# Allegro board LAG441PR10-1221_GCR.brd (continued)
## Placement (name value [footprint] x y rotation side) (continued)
PR180  1M_0402_1%  [R_0402]  16.89 42.61 180 top
PR181  499K_0402_1%  [R_0402]  21.2 40.9 90 top
PR182  47K_0402_1%  [R_0402]  16.89 44.26 180 top
PR183  499K_0402_1%  [R_0402]  26.25 46.6 270 top
PR184  221K_0402_1%  [R_0402]  19.4 44.5 90 top
PR185  1M_0402_1%  [R_0402]  43.22 13.22 270 top
PR186  0_0402_5%  [R0402_0OHM]  16.03 41.87 270 top
PR187  47K_0402_1%  [R_0402]  22.85 42.69 90 top
PR188  0_0402_5%  [R0402_0OHM]  25.27 43.53 270 top
PR189  1M_0201_1%  [R_0201]  15.72 40.1 180 top
PR190  200K_0402_1%  [R_0402]  25.48 45.69 90 top
PR191  1M_0201_1%  [R_0201]  25.96 43.68 0 top
PR192  200K_0402_1%  [R_0402]  20.44 41.81 270 top
PR193  200K_0402_1%  [R_0402]  21.2 42.59 90 top
PR194  200K_0402_1%  [R_0402]  21.06 45.51 270 top
PR195  100_0402_1%  [R_0402]  39.84 19.7 0 top
PR196  100_0402_1%  [R_0402]  39.84 18.94 0 top
PR197  0_0402_5%  [R0402_0OHM]  40.75 18.18 180 top
PR199  0_0402_5%  [R0402_0OHM]  22.8 40 270 top
PR200  0.01_1206_1%  [R_1206_4P-D]  22.38 39.17 180 bottom
PR201  442K_0402_1%  [R_0402]  21.55 41.52 270 bottom
PR202  1_0402_1%  [R_0402]  26.26 23.69 270 top
PR203  1_0402_1%  [R_0402]  27.15 23.69 270 top
PR204  100K_0402_1%  [R_0402]  21.49 43.26 0 bottom
PR205  2.2_0603_5%  [R_0603]  30.45 22.37 180 top
PR206  2_1206_5%  [R_1206]  23.79 25.21 270 top
PR207  4.7_0402_1%  [R_0402]  34.12 20.59 0 top
PR208  2_1206_5%  [R_1206]  19.4 20.66 0 top
PR209  0_0201_5%  [R_0201]  23.54 18.83 0 top
PR210  2.2_0603_5%  [R_0603]  33.5 19.58 0 top
PR211  0.005_1206_1%  [R_1206_4P-D]  44.93 27.83 270 bottom
PR212  0_0201_5%  [R0201_0OHM]  23.54 18.26 0 top
PR213  0_0402_5%  [R0402_0OHM]  23.54 17.57 0 top
PR214  0_0402_5%  [R0402_0OHM]  23.54 16.81 0 top
PR215  4.7_1206_5%  [R_1206]  24.73 32.08 270 top
PR216  4.7_1206_5%  [R_1206]  34.3 32.42 270 top
PR217  75_0402_5%  [R_0402]  23.54 16.05 0 top
PR218  0_0402_5%  [R0402_0OHM]  33.91 17.16 0 top
PR219  100K_0402_1%  [R_0402]  21.92 15.28 0 top
PR220  0_0402_5%  [R0402_0OHM]  23.54 15.28 0 top
PR221  1_0402_1%  [R_0402]  34.82 16.4 180 top
PR222  1_0402_1%  [R_0402]  35.62 15.55 270 top
PR223  0_0402_5%  [R0402_0OHM]  26.84 10.21 180 top
PR224  1M_0402_1%  [R_0402]  23.54 14.52 0 top
PR225  154K_0402_1%  [R_0402]  22.83 14.52 180 top
PR226  105K_0402_1%  [R_0402]  26.01 13.85 270 top
PR227  1M_0402_1%  [R_0402]  25.88 11.15 90 top
PR228  0_0201_5%  [R0201_0OHM]  25.27 13.33 90 top
PR229  0_0201_5%  [R0201_0OHM]  29.44 13.57 90 top
PR230  1K_0402_1%  [R_0402]  28.67 13.85 270 top
PR231  499_0402_1%  [R_0402]  26.77 13.85 270 top
PR232  10K_0201_5%  [R_0201]  29.44 12.95 270 top
PR233  0_0402_5%  [R0402_0OHM]  27.78 10.14 90 top
PR234  0_0402_5%  [R0402_0OHM]  28.67 10.14 90 top
PR236  100_0402_1%  [R_0402]  32.12 13.69 0 top
PR300  0_0603_5%  [R_0603]  200.8 46.03 90 bottom
PR302  52.3K_0402_1%  [R_0402]  202.16 42.13 270 bottom
PR304  11.5K_0402_1%  [R_0402]  201.4 41.22 90 bottom
PR306  0_0402_5%  [R0402_0OHM]  204.14 40.34 180 bottom
PR307  243K_0402_1%  [R_0402]  201.51 43.57 270 top
PR308  4.53K_0402_1%  [R_0402]  200.06 43.63 90 top
PR309  4.7_0805_5%  [R_0805]  198.13 55.5 0 bottom
PR310  10K_0402_1%  [R_0402]  203.22 39.58 0 bottom
PR400  0_0402_5%  [R_0402]  44.44 44.09 180 bottom
PR401  3.3_0603_1%  [R_0603]  40.24 42.38 180 top
PR402  4.7_0805_5%  [R_0805]  38.01 39.68 180 top
PR403  100K_0402_5%  [R_0402]  42.53 39.52 180 top
PR404  0_0402_5%  [R0402_0OHM]  42.71 44.04 270 bottom
PR408  0_0402_5%  [R_0402]  300.06 59.2 270 bottom
PR409  3.3_0603_1%  [R_0603]  298.04 62.69 90 top
PR410  4.7_0805_5%  [R_0805]  298.19 66.57 180 top
PR411  100K_0402_5%  [R_0402]  294.05 58.82 180 bottom
PR412  100K_0402_5%  [R_0402]  297.65 59.88 0 top
PR413  100K_0402_5%  [R_0402]  41.95 43.12 90 bottom
PR414  100K_0402_5%  [R_0402]  298.56 59.07 180 top
PR501  499_0402_1%  [R_0402]  113.64 26.33 0 bottom
PR502  40.2K_0402_1%  [R_0402]  115.45 27.21 270 bottom
PR503  150K_0201_5%  [R_0201]  113.64 21.01 180 bottom
PR504  20K_0402_1%  [R_0402]  115.89 25.55 180 bottom
PR506  4.7_0603_5%  [R_0603]  110.12 21.44 180 bottom
PR507  2.2_0402_1%  [R_0402]  112.15 22.17 270 bottom
PR510  274K_0402_1%  [R_0402]  112.87 25.5 90 bottom
PR600  75_0402_5%  [R_0402]  46.65 26.29 90 bottom
PR602  4.7_0603_5%  [R_0603]  47.94 20.11 0 top
PR603  0_0603_5%  [R_0603]  47.98 22.5 180 top
PR604  0_0402_5%  [R_0402]  46.48 24.67 90 top
PR605  100K_0402_1%  [R_0402]  50.64 24.27 180 top
PR606  100K_0402_1%  [R_0402]  48.86 24.3 270 top
PR607  0_0402_5%  [R_0402]  46.65 25.49 270 bottom
PR701  549K_0402_1%  [R_0402]  126.05 42.02 180 bottom
PR702  100K_0402_5%  [R_0402]  123.99 35.69 90 bottom
PR703  100K_0402_5%  [R_0402]  124.75 35.69 90 bottom
PR704  100K_0402_5%  [R_0402]  130.72 40.95 180 bottom
PR705  1M_0402_5%  [R_0402]  122.82 39.45 90 bottom
PR706  100K_0402_5%  [R_0402]  129.81 40.09 0 bottom
PR800  4.7_0805_5%  [R_0805]  123.9 57.28 180 top
PR801  0_0402_5%  [R_0402]  124.65 56.01 0 bottom
PR803  15K_0402_1%  [R_0402]  118.02 54.44 0 bottom
PR806  20K_0402_1%  [R_0402]  118.91 53.65 180 bottom
PR807  0_0402_5%  [R_0402]  118.01 52.07 0 bottom
PR808  0_0402_5%  [R_0402]  118.91 52.86 180 bottom
PR900  2M_0402_5%  [R_0402]  40.91 61.37 270 top
PR901  0_0402_5%  [R0402_0OHM]  46.33 54.07 270 bottom
PR902  4.7_0402_5%  [R_0402]  39.73 57.84 90 bottom
PR903  0_0402_5%  [R0402_0OHM]  40.65 57.7 180 top
PR904  0_0402_5%  [R0402_0OHM]  40.66 56.92 180 top
PR905  133K_0402_1%  [R_0402]  40.06 60.43 90 top
PR906  0_0402_5%  [R0402_0OHM]  40.66 56.13 180 top
PR907  0_0402_5%  [R0402_0OHM]  40.65 55.37 180 top
PR908  10K_0402_1%  [R_0402]  43.84 53.28 90 top
PR909  10K_0402_1%  [R_0402]  41.5 53.28 90 top
PR910  10K_0402_1%  [R_0402]  40.74 53.28 90 top
PR911  0_0402_5%  [R0402_0OHM]  39.98 53.28 90 top
PR912  10K_0402_1%  [R_0402]  45.44 53.29 90 top
PR913  45.3_0402_1%  [R_0402]  48.62 52.21 90 top
PR914  75_0402_1%  [R_0402]  45.31 52.52 0 top
PR915  100_0402_1%  [R_0402]  47.77 51.62 90 top
PR916  0_0402_5%  [R0402_0OHM]  42.26 53.28 90 top
PR917  1.5K_0402_1%  [R_0402]  44.55 62.81 90 top
PR918  1.5K_0402_1%  [R_0402]  43.79 62.81 90 top
PR919  0_0402_5%  [R0402_0OHM]  43.05 53.28 90 top
PR920  75_0402_5%  [R_0402]  44.65 53.3 90 top
PR921  1.5K_0402_1%  [R_0402]  43.03 62.81 90 top
PR922  0_0402_5%  [R0402_0OHM]  48.6 54.78 270 top
PR923  49.9_0402_1%  [R_0402]  47.75 53.29 90 top
PR924  1.5K_0402_1%  [R_0402]  42.26 62.81 90 top
PR925  0_0402_5%  [R0402_0OHM]  45.31 51.73 0 top
PR926  0_0402_5%  [R0402_0OHM]  46.2 53.29 90 top
PR927  0_0402_5%  [R0402_0OHM]  46.99 51.62 90 top
PR928  10_0402_1%  [R_0402]  46.99 53.29 90 top
PR929  1.47K_0402_1%  [R_0402]  45.39 62.76 0 top
PR930  0_0402_5%  [R0402_0OHM]  48.83 54.36 180 bottom
PR931  10K_0402_1%  [R_0402]  47.09 53.16 90 bottom
PR932  6.2K_0402_1%  [R_0402]  39.99 58.74 90 top
PR933  100K_0402_1%  [R_0402]  46.33 64.59 90 top
PR934  0_0402_5%  [R0402_0OHM]  39.21 58.73 90 top
PR935  0_0402_5%  [R0402_0OHM]  40.99 56.09 270 bottom
PR936  61.9K_0402_1%  [R_0402]  51.06 55.2 180 bottom
PR937  10K_0402_1%  [R_0402]  41.91 54.35 180 bottom
PR938  2.49K_0402_1%  [R_0402]  47.14 62.76 0 top
PR939  53.6K_0402_1%  [R_0402]  51.05 60.31 180 bottom
PR940  100K_0402_1%  [R_0402]  48.08 64.59 90 top
PR941  121K_0402_1%  [R_0402]  51.05 57.72 180 bottom
PR942  620K_0402_1%  [R_0402]  51.06 56 180 bottom
PR943  8.2K_0402_1%  [R_0402]  50.05 61.08 90 bottom
PR944  49.9K_0402_1%  [R_0402]  39.71 59.64 90 bottom
PR945  100K_0402_1%  [R_0402]  49 62.81 90 top
PR1000  0_0402_5%  [R0402_0OHM]  77.38 75.71 180 top
PR1001  0_0402_5%  [R0402_0OHM]  75.22 75.08 180 top
PR1002  0_0402_5%  [R0402_0OHM]  75.22 75.84 180 top
PR1003  4.7_0805_5%  [R_0805]  80.3 73.75 270 top
PR1009  0_0402_5%  [R0402_0OHM]  110.72 68.79 180 bottom
PR1010  0_0402_5%  [R0402_0OHM]  111.2 69.65 90 top
PR1011  0_0402_5%  [R0402_0OHM]  112.03 69.65 90 top
PR1012  4.7_0805_5%  [R_0805]  105.89 69.26 180 top
PR1100  0_0402_5%  [R0402_0OHM]  43.45 52.94 0 bottom
PR1101  0_0402_5%  [R0402_0OHM]  42.46 52.85 270 bottom
PR1102  0_0402_5%  [R0402_0OHM]  41.67 52.85 270 bottom
PR1103  4.7_0805_5%  [R_0805]  44.25 47.18 0 top
PR1104  0_0402_5%  [R0402_0OHM]  129.85 66.63 0 top
PR1105  0_0402_5%  [R0402_0OHM]  129.89 67.75 0 top
PR1106  4.7_0805_5%  [R_0805]  128.19 63.53 180 top
PR1107  0_0402_5%  [R0402_0OHM]  129.89 68.54 0 top
PR1204  0_0402_5%  [R0402_0OHM]  26.96 43.02 270 top
PR1400  10K_0402_1%  [R_0402]  100.29 19.07 0 bottom
PR1401  0_0402_5%  [R_0402]  100.29 19.83 0 bottom
PR1402  100K_0402_5%  [R_0402]  107.06 16.64 0 bottom
PR1403  5.1_0402_1%  [R_0402]  108.02 20.38 0 bottom
PR1404  2.2_0402_1%  [R_0402]  105.73 21.65 0 bottom
PR1405  10K_0402_1%  [R_0402]  100.29 16.02 0 bottom
PR1406  10K_0402_1%  [R_0402]  100.29 17.54 0 bottom
PR1407  4.7_0603_5%  [R_0603]  101.49 22.23 90 bottom
PR1408  0_0402_5%  [R0402_0OHM]  101.21 21.35 180 bottom
PR1409  0_0402_5%  [R_0402]  106.98 18.18 0 bottom
PR1410  10K_0402_1%  [R_0402]  101.21 16.78 180 bottom
PR1411  10K_0402_1%  [R_0402]  101.21 18.31 180 bottom
PR1412  0_0402_5%  [R0402_0OHM]  106.98 18.94 0 bottom
PR1413  150K_0402_1%  [R_0402]  125.17 46.2 270 top
PR1414  10K_0402_1%  [R_0402]  125.9 43.28 90 bottom
PR1415  0_0402_5%  [R0402_0OHM]  125.14 43.28 90 bottom
PR1416  2.2_0402_1%  [R_0402]  124.31 48.6 90 bottom
PR1417  4.7_0603_5%  [R_0603]  122.54 48.94 180 bottom
PR1418  0_0402_5%  [R0402_0OHM]  126.99 51.09 0 bottom
PR1419  0_0402_5%  [R_0402]  126.99 50.32 0 bottom
PR1420  10K_0402_1%  [R_0402]  130.36 43.3 90 bottom
PR1421  10K_0402_1%  [R_0402]  128.69 42.49 90 bottom
PR1423  5.1_0402_1%  [R_0402]  124.47 50.35 180 bottom
PR1424  0_0402_5%  [R0402_0OHM]  106.98 17.42 0 bottom
PR1425  100K_0402_5%  [R_0402]  128.7 50.29 90 bottom
PR1426  10K_0402_1%  [R_0402]  130.35 45.01 0 bottom
PR1427  10K_0402_1%  [R_0402]  127.86 43.4 270 bottom
PR1428  0_0402_5%  [R0402_0OHM]  127.83 44.18 0 bottom
PR1429  0_0402_5%  [R0402_0OHM]  129.54 45.07 270 bottom
PR1430  0_0402_5%  [R0402_0OHM]  100.29 20.59 0 bottom
PR1431  0_0402_5%  [R_0402]  19.43 63.89 180 top
PR1432  0_0402_5%  [R_0402]  8.29 43 90 top
PR1500  0_0402_5%  [R_0402]  83.08 71.72 180 top
PR1501  0_0402_5%  [R_0402]  39.53 33.81 0 top
PR1502  0_0402_5%  [R_0402]  36.97 37.08 270 top
PR1503  0_0402_5%  [R_0402]  89.24 69.46 180 top
PR1504  300K_0402_1%  [R_0402]  84.28 71.6 0 top
PR1505  237K_0402_1%  [R_0402]  39.43 32.14 90 top
PR1506  0_0402_5%  [R_0402]  22.33 8.83 0 top
PR1507  0_0402_5%  [R0402_0OHM]  29.26 56.22 90 top
PR1508  0_0402_5%  [R0402_0OHM]  28.6 54.67 270 top
PR1509  0_0402_5%  [R0402_0OHM]  22.71 63.57 180 top
PR1510  0_0402_5%  [R0402_0OHM]  19.43 65.08 90 top
PR1511  0_0402_5%  [R0402_0OHM]  126.08 36.58 270 bottom
PR1512  287K_0402_1%  [R_0402]  81.98 75.34 270 top
PR1513  100K_0402_5%  [R_0402]  85.79 73.13 0 top
PR1514  200K_0402_1%  [R_0402]  86.02 72.27 0 top
PR1515  43.2K_0402_1%  [R_0402]  39.45 30.47 90 top
PR1516  4.32K_0402_1%  [R_0402]  39.32 28.3 0 top
PR1517  14.7K_0402_1%  [R_0402]  37.02 28.81 180 top
PR1518  14.7K_0402_1%  [R_0402]  37.02 29.6 180 top
PR1519  100K_0402_5%  [R_0402]  131.45 36.9 270 bottom
PR1567  -  [SOLDER_PREFORMS_0603]  66.24 74.3 0 bottom
PR1568  -  [SOLDER_PREFORMS_0603]  126.96 72.52 180 bottom
PRB36  0_0402_5%  [R_0402]  26.3 39.24 180 top
PRB37  0_0402_5%  [R_0402]  23.6 37.15 0 top
PRB39  0_0402_5%  [R0402_0OHM]  29.77 40.29 180 top
PRB40  100K_0402_1%  [R_0402]  32.55 36.4 90 top
PRB41  100K_0402_1%  [R_0402]  28.54 36 90 top
PRB42  0_0402_5%  [R0402_0OHM]  31.69 37.32 270 top
PRB45  0_0402_5%  [R_0402]  29.65 36.4 0 top
PRB46  0_0402_5%  [R0402_0OHM]  23.57 39.24 0 top
PRB47  0_0402_5%  [R0402_0OHM]  23.6 38 0 top
PT100  PAD~D  [TPC12]  10.71 74.64 0 top
PT101  PAD~D  [TPC12]  10.79 72.21 0 top
PT102  PAD~D  [TPC12]  12.15 73.45 0 top
PT103  PAD~D  [TPC12]  11.16 58.9 180 top
PT104  PAD~D  [TPC12]  9.7 57.99 180 top
PT105  PAD~D  [TPC12]  9.69 59.99 270 top
PT200  PAD~D  [TPC12]  22.58 38.08 270 top
PTB2  PAD~D  [TPC12]  26.3 40.63 0 top
PU101  -  [AZV3001FZ47_X2DFN1410-6_1P4X1]  18.21 43.62 270 top
PU102  -  [AZV3001FZ47_X2DFN1410-6_1P4X1]  23.29 44.48 90 top
PU200  -  [ISL9538BHRTZ-T_TQFN32_4X4]  30.64 16.31 180 top
PU300  -  [MP8733AGLE-Z_QFN21_3X4]  200.03 44.51 180 bottom
PU400  -  [NB679AGD-Z_QFN12_2X3]  42.37 40.86 180 bottom
PU401  -  [NB679AGD-Z_QFN12_2X3]  297.49 58.9 90 bottom
PU500  -  [NB591GG-Z_QFN11_2X2]  115.11 23.48 180 bottom
PU600  -  [SY8210AQVC_QFN19_4X3]  50.68 26.62 180 bottom
PU700  -  [SN74LVC1G123DCUR_VSSOP8]  125.5 37.81 180 bottom
PU800  -  [SY8286RAC_QFN20_3X3]  123.42 55.01 180 bottom
PU900  -  [MP2979AGQKT-0030-Z_TQFN48_6X6]  43.19 61.74 270 bottom
PU1000  -  [MP86901-CGLT-Z_TQFN21_3X4]  75.54 73.88 180 bottom
PU1001  -  [MP86901-CGLT-Z_TQFN21_3X4]  110.21 71.77 0 bottom
PU1100  -  [MP86901-CGLT-Z_TQFN21_3X4]  43.99 49.83 180 bottom
PU1101  -  [MP86901-AGQT-Z_TQFN13_3X3]  128.97 65.86 90 bottom
PU1400  -  [NB692GD-Z_QFN13_2X3]  104.6 18.12 90 bottom
PU1401  -  [NB692GD-Z_QFN13_2X3]  127.25 47.74 180 bottom
PU1500  -  [AZV3001FZ47_X2DFN1410-6_1P4X1]  84.48 72.86 90 top
PU1501  -  [AZV3001FZ47_X2DFN1410-6_1P4X1]  37.64 32.12 0 top
PUB2  -  [MC74VHC1G08DFT2G_SC70-5]  28.69 39.26 270 top
Q3  -  [DMN2400UV-7_SOT-563-6]  198.67 19.7 270 bottom
Q12  -  [DMN2400UV-7_SOT-563-6]  198.8 65.46 0 bottom
Q13  -  [DMN2400UV-7_SOT-563-6]  194.98 20.72 90 bottom
Q14  -  [DMN2400UV-7_SOT-563-6]  296.68 68.99 90 top
Q15  -  [DMN2400UV-7_SOT-563-6]  296.68 71.78 90 top
QB5  -  [DMG2301U-7_SOT23-3]  311.63 6.18 0 top
QB6  -  [DMN2400UV-7_SOT-563-6]  308.27 1.8 0 top
QC1  -  [DMN2400UV-7_SOT-563-6]  121.63 32.62 270 bottom
QC2  2N7002KW_SC-70-3  [L2N7002WT1G_SC-70-3]  114.78 49.9 270 bottom
QC3  -  [DMG2301U-7_SOT23-3]  115.85 45.29 180 bottom
QE1  2N7002KW_SC-70-3  [L2N7002WT1G_SC-70-3]  251.5 56.46 90 top
QE4  2N7002KW_SC-70-3  [L2N7002WT1G_SC-70-3]  104.19 66.78 0 top
QE5  -  [LMBT3904WT1G_SC70-3]  107.47 66.77 180 top
QE8  PMBT3904MB_SOT883B  [PMZ370UNE_DFN1006-3]  255.62 59.3 180 top
QE10  2N7002KW_SC-70-3  [L2N7002WT1G_SC-70-3]  253.37 53.92 270 top
QE11  2N7002KW_SC-70-3  [L2N7002WT1G_SC-70-3]  253.37 51.31 270 top
QE12  PMBT3904MB_SOT883B  [PMZ370UNE_DFN1006-3]  79.84 41.33 180 top
QE14  PMBT3904MB_SOT883B  [PMZ370UNE_DFN1006-3]  95.34 13.78 180 top
QE17  PMBT3904MB_SOT883B  [PMZ370UNE_DFN1006-3]  192.09 55.39 270 bottom
QE23  PMBT3904MB_SOT883B  [PMZ370UNE_DFN1006-3]  36.57 15.76 0 top
QE26  2N7002KW_SC-70-3  [L2N7002WT1G_SC-70-3]  276.85 51.9 0 top
QK1  LN2316ELT1G_SOT23-3  [DMG6968U-7_SOT23-3]  215.37 17.19 180 top
QK2  -  [DMG2301U-7_SOT23-3]  246.25 13.1 90 top
QK3  2N7002KW_SC-70-3  [L2N7002WT1G_SC-70-3]  241.53 13.1 270 top
QK4  2N7002KW_SC-70-3  [L2N7002WT1G_SC-70-3]  241.53 15.64 270 top
QK5  -  [DMG2301U-7_SOT23-3]  246.25 17.04 90 top
QM1  -  [DMN2400UV-7_SOT-563-6]  16.67 23.32 0 bottom
QM2  2N7002KW_SC-70-3  [L2N7002WT1G_SC-70-3]  16.42 25.14 270 bottom
QM3  2N7002KW_SC-70-3  [L2N7002WT1G_SC-70-3]  17.12 24.84 0 top
QN2  2N7002KW_SC-70-3  [L2N7002WT1G_SC-70-3]  254.06 49.15 0 top
QN3  2N7002KW_SC-70-3  [L2N7002WT1G_SC-70-3]  262.93 42.12 180 top
QN4  -  [DMN2400UV-7_SOT-563-6]  270.22 34.98 180 top
QN5  -  [DMN2400UV-7_SOT-563-6]  209.66 25.63 0 top
QN6  2N7002KW_SC-70-3  [L2N7002WT1G_SC-70-3]  251.31 49.17 0 top
QN7  -  [DMN2400UV-7_SOT-563-6]  263.24 24.28 270 top
QN8  -  [DMN2400UV-7_SOT-563-6]  260.83 30.75 90 top
QN9  -  [DMN2400UV-7_SOT-563-6]  221.33 27.2 180 top
QN10  LN2316ELT1G_SOT23-3  [DMG6968U-7_SOT23-3]  222.87 37.1 270 top
QN11  2N7002KW_SC-70-3  [L2N7002WT1G_SC-70-3]  288.77 71.45 180 bottom
QN12  -  [DMN2400UV-7_SOT-563-6]  272.85 27.31 0 top
QR1  2N7002KW_SC-70-3  [L2N7002WT1G_SC-70-3]  292.83 41.17 270 top
QT1  -  [DMN65D8LW-7_SOT323-3]  9.89 72.73 270 bottom
QT2  S TR AO7401 1P SC70-3  [SI1303DL-T1-E3_SOT323-3]  13.33 72.66 90 bottom
QT3  -  [L2N7002DW1T1G_SC88-6]  16.41 73.49 0 bottom
QT4  S TR AO7401 1P SC70-3  [SI1303DL-T1-E3_SOT323-3]  17.86 68.73 270 bottom
QV1  -  [DMG2301U-7_SOT23-3]  62.29 60.05 270 bottom
QV4  -  [MMBT3906H_SOT23-3]  55.94 63.07 90 top
QV5  -  [LMBT3904WT1G_SC70-3]  58.69 61.74 0 top
QV6  -  [MMBT3906H_SOT23-3]  66.36 63.07 90 top
QV7  -  [LMBT3904WT1G_SC70-3]  70.46 63.46 90 top
QV10  -  [SI3457BDV-T1-E3_TSOP6]  31.8 69.54 0 top
QV11  -  [L2N7002DW1T1G_SC88-6]  35.21 66.39 90 top
QV12  -  [DMG2301U-7_SOT23-3]  303.79 61.96 270 bottom
QZ20  -  [LMUN5111T1G_SC70-3]  146.41 17.96 90 bottom
QZ21  -  [LMBT3904WT1G_SC70-3]  150.58 17.52 180 bottom
R20  1.2K_0402_5%  [R_0402]  291.06 72.46 90 bottom
R23  10K_0201_5%  [R_0201]  203.3 29.61 90 bottom
R24  10K_0201_5%  [R_0201]  203.3 28.97 270 bottom
R26  0.5A_65V_T0603FF0500TM  [F_T0603FF0500TM]  47 74.89 90 top
R27  0_0603_5%  [R0603_0OHM]  186.66 19.07 0 bottom
R28  100K_0201_5%  [R_0201]  185.01 12.76 270 bottom
R31  0_0603_5%  [R0603_0OHM]  256.39 37.1 270 top
R33  0_0603_5%  [R0603_0OHM]  253.88 37.1 270 top
R43  0_0603_5%  [R0603_0OHM]  200.38 33.42 0 top
R44  0_0603_5%  [R0603_0OHM]  200.14 30.52 0 top
R46  0_0603_5%  [R0603_0OHM]  224.07 61.8 180 top
R47  0_0603_5%  [R0603_0OHM]  222.22 49.87 270 top
R58  0_0603_5%  [R0603_0OHM]  121.77 30.05 180 top
R59  0_0603_5%  [R0603_0OHM]  126.16 30.73 0 top
R101  300_0402_5%  [R_0402]  115.81 52.76 90 bottom
R102  1.58K_0402_1%  [R_0402]  200.44 62.71 270 bottom
R103  0_0603_5%  [R0603_0OHM]  96.3 18.75 0 bottom
R139  300_0402_5%  [R_0402]  200.44 59.2 270 bottom
R140  300_0402_5%  [R_0402]  200.44 59.94 90 bottom
R145  100K_0201_5%  [R_0201]  49.15 69.78 270 top
R151  300_0402_5%  [R_0402]  142.91 17.66 270 bottom
R152  300_0402_5%  [R_0402]  142.91 19.32 270 bottom
R205  0_0603_5%  [R0603_0OHM]  227.43 48.09 90 top
R206  0_0603_5%  [R0603_0OHM]  79.29 59.9 90 bottom
R207  0_0603_5%  [R0603_0OHM]  97 60.85 180 bottom
R208  0_0201_5%  [R0201_0OHM]  229.42 42.94 0 top
R209  25.5K_0402_1%  [R_0402]  228.5 48.41 0 top
R210  20K_0201_1%  [R_0201]  230.1 48.11 90 top
R217  100K_0201_5%  [R_0201]  296.3 68.17 0 top
R218  100K_0201_5%  [R_0201]  295.62 68.17 180 top
R219  100K_0201_5%  [R_0201]  296.89 70.92 180 top
R220  100K_0201_5%  [R_0201]  303.9 65.39 180 bottom
R221  100K_0201_5%  [R_0201]  310.11 63.1 90 top
R222  0_0201_5%  [R_0201]  47.99 69.2 90 top
R223  0_0201_5%  [R0201_0OHM]  48.56 69.2 90 top
R229  10K_0201_5%  [R_0201]  200.89 31.04 270 bottom
R238  100K_0201_5%  [R_0201]  99.19 20.52 270 top
R240  100K_0201_5%  [R_0201]  82.21 63.73 90 bottom
R241  0_0201_5%  [R_0201]  67.73 65.7 90 top
R242  100K_0201_5%  [R_0201]  67.16 66.29 270 top
R243  0_0201_5%  [R0201_0OHM]  40.23 57.04 0 bottom
R246  0_0201_5%  [R0201_0OHM]  184.38 12.17 90 bottom
R247  0_0201_5%  [R0201_0OHM]  101.98 65.26 270 bottom
R248  0_0201_5%  [R_0201]  102.56 64.08 180 bottom
R249  0_0201_5%  [R0201_0OHM]  98.59 21.11 0 top
R250  0_0201_5%  [R0201_0OHM]  97.98 21.37 180 top
R256  0_0402_5%  [R_0402]  301.98 64.32 90 bottom
R258  0_0201_5%  [R0201_0OHM]  300.93 57.8 90 bottom
R266  100K_0201_5%  [R_0201]  255.5 42.08 90 top
R267  100K_0201_5%  [R_0201]  225.36 53.74 0 top
R268  0_0201_5%  [R_0201]  227.18 55.35 90 top
R271  0_0201_5%  [R0201_0OHM]  142.73 20.1 180 bottom
R272  330K_0201_1%  [R_0201]  130.31 16.31 90 bottom
R273  0_0201_5%  [R0201_0OHM]  107.61 67.79 180 top
R274  10K_0201_5%  [R_0201]  284.45 69.32 90 bottom
R275  0_0402_5%  [R_0402]  186.47 12.79 270 bottom
R276  0_0201_5%  [R_0201]  308.65 61.38 90 top
R277  0_0201_5%  [R_0201]  308.08 61.38 90 top
R278  0_0201_5%  [R0201_0OHM]  308.65 61.38 90 bottom
R279  0_0201_5%  [R0201_0OHM]  308.08 61.38 90 bottom
R280  0_0201_5%  [R_0201]  103.15 64.66 180 bottom
R281  0_0201_5%  [R_0201]  86.77 62.93 0 bottom
R282  0_0201_5%  [R0201_0OHM]  88.54 62.93 180 bottom
R283  1M_0201_5%  [R_0201]  127.46 28 0 top
R284  0_0603_5%  [R0603_0OHM]  304.61 60.33 0 bottom
RA1  0_0402_5%  [R0402_0OHM]  289.79 17.53 90 top
RA2  1K_0201_5%  [R_0201]  292.2 28.09 270 top
RA4  0_0201_5%  [R_0201]  292.39 26.88 0 top
RA5  0_0402_5%  [R0402_0OHM]  288.52 17.16 90 top
RA6  0_0402_5%  [R0402_0OHM]  288.01 32.4 270 bottom
RA7  1K_0201_5%  [R_0201]  291.63 28.09 270 top
RA8  1K_0201_5%  [R_0201]  294.3 25.8 90 top
RA9  0_0402_5%  [R0402_0OHM]  275.96 24.52 0 top
RA10  0_0201_5%  [R0201_0OHM]  293.53 18.6 270 top
RA11  0_0402_5%  [R_0402]  275.96 25.34 0 top
RA12  100K_0201_5%  [R_0201]  290.33 27.01 180 top
RA13  0_0402_5%  [R0402_0OHM]  284.52 17.62 270 top
RA14  0_0402_5%  [R0402_0OHM]  279.93 18.43 0 top
RA15  0_0402_5%  [R_0402]  279.93 17.67 0 top
RA16  33_0201_5%  [R_0201]  280.75 19.13 180 top
RA21  BLM15HD601SN1D_0402  [R_0402]  277.42 23.64 0 top
RA22  100K_0201_1%  [R_0201]  279.02 29.03 90 top
RA23  BLM15HD601SN1D_0402  [R_0402]  277.42 22.87 0 top
RA29  200K_0402_1%  [R_0402]  278.34 29.09 90 top
RA30  16.2_0402_1%  [R_0402]  291.31 23.77 0 top
RA31  16.2_0402_1%  [R_0402]  290.73 20.21 0 top
RA33  2.2K_0201_5%  [R_0201]  288.9 20.97 0 top
RA34  2.2K_0201_5%  [R_0201]  289.03 21.61 90 top
RA109  0_0201_5%  [R0201_0OHM]  297.15 16.11 90 top
RA110  10K_0201_5%  [R_0201]  296.52 16.11 90 top
RA112  0_0603_1%  [R0603_0OHM]  282.5 15.23 90 top
RA115  0_0603_1%  [R0603_0OHM]  265.09 37.1 270 top
RA116  0_0603_1%  [R0603_0OHM]  267.44 37.1 270 top
RA117  0_0201_5%  [R_0201]  275.21 26.75 0 top
RA118  10K_0201_5%  [R_0201]  278.8 26.14 90 top
RA120  0_0201_5%  [R_0201]  276.41 26.75 0 top
RA121  1K_0201_5%  [R_0201]  278.19 27.32 0 top
RA122  0_0201_5%  [R0201_0OHM]  266.61 42.67 270 top
RA123  0_0201_5%  [R_0201]  292.96 18.6 270 top
RA124  100K_0201_5%  [R_0201]  278.46 28.39 0 top
RA125  0_0201_5%  [R0201_0OHM]  303 25.42 270 top
RA126  10K_0201_5%  [R_0201]  280.17 11.54 270 top
RB21  1K_0201_1%  [R_0201]  308.76 8.73 0 top
RB22  10K_0201_5%  [R_0201]  310.04 3.45 270 top
RB23  1M_0201_5%  [R_0201]  311.92 1.8 180 top
RB24  0_0201_5%  [R0201_0OHM]  312.61 1.8 0 top
RB25  100K_0201_5%  [R_0201]  312.3 3.96 0 top
RB34  100K_0201_5%  [R_0201]  276.17 62.38 180 top
RB35  75_0201_1%  [R_0201]  310.04 1.67 90 top
RB36  0_0603_5%  [R0603_0OHM]  271.01 15.77 90 top
RB37  0_0603_5%  [R0603_0OHM]  269.76 15.77 90 top
RB38  0_0603_5%  [R0603_0OHM]  267.27 15.75 90 top
RB39  0_0603_5%  [R0603_0OHM]  268.52 15.77 90 top
RB40  200_0201_1%  [R_0201]  309.35 7.43 90 top
RC1  2.2K_0201_5%  [R_0201]  102.36 50.69 0 top
RC2  100K_0201_5%  [R_0201]  111.76 52.29 0 bottom
RC3  2.2K_0201_5%  [R_0201]  102.36 50.06 0 top
RC4  100K_0201_5%  [R_0201]  108.64 52.43 0 top
RC5  2.2K_0201_5%  [R_0201]  105.93 58.02 270 bottom
RC6  100K_0201_5%  [R_0201]  108.64 51.87 0 top
RC7  2.2K_0201_5%  [R_0201]  105.85 58.63 0 bottom
RC8  24.9_0201_1%  [R_0201]  83.48 51.47 90 top
RC10  200_0201_1%  [R_0201]  107.67 46.28 270 top
RC11  200_0201_1%  [R_0201]  95.99 39.92 90 top
RC12  80.6_0201_1%  [R_0201]  96.57 39.91 90 top
RC13  162_0201_1%  [R_0201]  97.13 39.92 90 top
RC17  10K_0201_5%  [R_0201]  104.27 42.82 0 top
RC18  1K_0201_5%  [R_0201]  119.23 32.85 180 bottom
RC19  33_0201_1%  [R_0201]  102.3 31.72 270 top
RC20  1K_0201_5%  [R_0201]  118.02 32.21 0 bottom
RC23  1K_0201_5%  [R_0201]  111.68 46.37 0 bottom
RC24  10K_0201_5%  [R_0201]  101.13 40.51 270 top
RC25  1K_0201_5%  [R_0201]  111.68 46.93 0 bottom
RC26  4.7K_0201_5%  [R_0201]  106.41 46.34 90 top
RC27  4.7K_0201_5%  [R_0201]  105.68 46.37 90 top
RC29  150K_0201_5%  [R_0201]  103.24 29.39 270 bottom
RC38  10K_0201_5%  [R_0201]  107.73 30.54 270 top
RC40  10K_0201_5%  [R_0201]  105.14 48.46 270 top
RC41  10K_0201_5%  [R_0201]  109.1 40.28 180 top
RC45  4.7K_0201_5%  [R_0201]  104.05 39.92 90 top
RC46  4.7K_0201_5%  [R_0201]  103.85 30.55 270 top
RC47  113_0201_1%  [R_0201]  103.67 52.66 180 top
RC48  0_0201_5%  [R0201_0OHM]  104 50.76 90 top
RC49  1K_0201_5%  [R_0201]  103.64 52.03 180 top
RC50  100_0201_1%  [R_0201]  104.56 52.09 90 top
RC53  10K_0201_5%  [R_0201]  107.35 52.05 270 top
RC54  10K_0201_5%  [R_0201]  106.21 52.67 90 top
RC55  10K_0201_5%  [R_0201]  106.13 50.63 270 top
RC57  1K_0201_5%  [R_0201]  102.21 28.67 0 top
RC58  10K_0201_5%  [R_0201]  104.88 29.86 90 top
RC59  200K _0201_1%  [R_0201]  108.33 59.61 180 bottom
RC60  0_0201_5%  [R_0201]  57.89 67.87 270 top
RC61  0_0201_5%  [R_0201]  57.31 67.87 270 top
RC62  10K_0201_5%  [R_0201]  104.88 31.15 90 top
RC63  10K_0201_5%  [R_0201]  106.91 40.51 270 top
RC65  10K_0201_5%  [R_0201]  104.88 28.68 90 top
RC66  10M_0201_5%  [R_0201]  98.53 26.56 180 bottom
RC67  10K_0201_5%  [R_0201]  106.34 40.51 270 top
RC68  20K_0201_5%  [R_0201]  98.91 29.39 270 bottom
RC71  20K_0201_5%  [R_0201]  97.53 28.4 0 bottom
RC73  1K_0201_5%  [R_0201]  99.47 27.02 90 top
RC74  10K_0201_5%  [R_0201]  98.89 27.02 90 top
RC76  100K_0201_5%  [R_0201]  99.92 22.37 0 bottom
RC77  100K_0201_5%  [R_0201]  96.18 21.93 90 bottom
RC78  330K_0201_1%  [R_0201]  98.27 30.63 270 bottom
RC79  1K_0201_5%  [R_0201]  94.32 60.2 180 bottom
RC80  8.2K_0201_5%  [R_0201]  100.81 28.81 90 bottom
RC81  10K_0201_5%  [R_0201]  103.35 30.6 270 bottom
RC82  10K_0201_5%  [R_0201]  100.81 30.63 270 bottom
RC85  0_0201_5%  [R_0201]  86.14 58.41 270 bottom
RC86  62_0201_1%  [R_0201]  93.6 58.46 270 bottom
RC87  1K_0201_5%  [R_0201]  52.81 67.87 270 top
RC88  10K_0201_5%  [R_0201]  113.11 50.86 0 bottom
RC89  1K_0201_5%  [R_0201]  52.23 67.87 270 top
RC90  0_0201_5%  [R_0201]  99.54 28.81 90 bottom
RC92  100K_0201_5%  [R_0201]  99.16 27.83 270 bottom
RC106  49.9_0201_1%  [R_0201]  97.7 39.92 90 top
RC107  49.9_0201_1%  [R_0201]  100.85 41.48 180 top
RC108  49.9_0201_1%  [R_0201]  70.73 52.67 270 top
RC109  49.9_0201_1%  [R_0201]  71.7 52.67 270 top
RC111  33_0201_1%  [R_0201]  97.64 29.99 90 bottom
RC112  33_0201_1%  [R_0201]  98.12 28.97 180 bottom
RC113  33_0201_1%  [R_0201]  96.24 29.99 90 bottom
RC116  200_0201_1%  [R_0201]  108.37 29.33 270 bottom
RC118  4.7K_0201_5%  [R_0201]  103.92 30.6 270 bottom
RC119  1K_0201_5%  [R_0201]  23.63 6.5 180 top
RC120  1K_0201_1%  [R_0201]  74.33 61.04 270 bottom
RC124  49.9_0201_1%  [R_0201]  77.57 52.6 90 top
RC125  1.5K_0201_5%  [R_0201]  55.37 65.53 180 top
RC150  100_0201_1%  [R_0201]  84.64 51.47 180 top
RC151  100_0201_1%  [R_0201]  83.96 53.23 180 top
RC153  0_0603_5%  [R0603_0OHM]  90.28 59.35 0 bottom
RC154  56_0201_5%  [R_0201]  77 59.14 270 bottom
RC155  220_0201_5%  [R_0201]  77 57.36 90 bottom
RC156  100_0201_5%  [R_0201]  77.57 59.14 270 bottom
RC157  0_0201_5%  [R0201_0OHM]  77.57 57.36 90 bottom
RC158  43_0201_5%  [R_0201]  78.14 59.14 270 bottom
RC159  0_0201_5%  [R0201_0OHM]  78.14 57.36 90 bottom
RC160  100_0201_1%  [R_0201]  62.96 48.93 90 bottom
RC161  100_0201_1%  [R_0201]  62.96 50.17 90 bottom
RC163  100_0201_1%  [R_0201]  92.98 40.39 270 top
RC164  100_0201_1%  [R_0201]  92.49 52.23 270 top
RC165  100_0201_1%  [R_0201]  92.39 39.81 90 top
RC166  100_0201_1%  [R_0201]  93.61 51.64 90 top
RC173  0_0603_5%  [R_0603]  100.77 60.41 270 bottom
RC175  0_0402_5%  [R_0402]  113.03 55.31 0 bottom
RC217  51_0201_5%  [R_0201]  80.24 57.95 270 bottom
RC218  1K_0201_5%  [R_0201]  94.33 59.63 270 bottom
RC219  49.9_0201_1%  [R_0201]  76.43 59.14 270 bottom
RC220  499_0201_1%  [R_0201]  76.3 52.6 90 top
RC221  1K_0201_5%  [R_0201]  75.67 53.23 270 top
RC222  0_0201_5%  [R0201_0OHM]  94.33 58.46 270 bottom
RC223  0_0201_5%  [R_0201]  65.01 58.49 0 bottom
RC225  100K_0201_5%  [R_0201]  51.1 67.29 90 top
RC226  1K_0402_5%  [R_0402]  55.43 66.17 90 top
RC227  0_0201_5%  [R_0201]  76.95 60.47 90 bottom
RC228  0_0201_5%  [R_0201]  71.16 60.47 90 bottom
RC229  0_0201_5%  [R_0201]  75.12 60.46 90 bottom
RC230  51_0201_5%  [R_0201]  77.57 62.25 270 bottom
RC231  0_0201_5%  [R_0201]  72.43 60.47 90 bottom
RC232  0_0201_5%  [R_0201]  79.68 57.37 90 bottom
RC233  0_0201_5%  [R_0201]  76.31 60.47 90 bottom
RC234  0_0201_5%  [R_0201]  75.68 60.47 90 bottom
RC235  0_0201_5%  [R_0201]  71.79 60.47 90 bottom
RC236  0_0201_5%  [R_0201]  79.13 57.37 90 bottom
RC237  0_0201_5%  [R_0201]  70.52 60.47 90 bottom
RC238  0_0201_5%  [R_0201]  50.53 67.29 90 top
RC239  51_0201_5%  [R_0201]  72.43 62.25 270 bottom
RC240  51_0201_5%  [R_0201]  74.97 62.25 270 bottom
RC241  1K_0201_5%  [R_0201]  58.5 66.1 90 top
RC242  100_0201_5%  [R_0201]  76.87 62.25 270 bottom
RC243  1K_0201_5%  [R_0201]  51.66 67.87 270 top
RC244  51_0201_5%  [R_0201]  71.16 62.25 270 bottom
RC245  0_0201_5%  [R_0201]  69.04 67.58 180 top
RC246  0_0201_5%  [R_0201]  67.72 67.4 180 top
RC247  0_0201_5%  [R_0201]  61.38 66.4 90 top
RC248  0_0201_5%  [R_0201]  53.38 67.29 90 top
RC249  0_0402_5%  [R_0402]  54.67 67.09 270 top
RC250  1K_0201_5%  [R_0201]  61.94 66.43 90 top
RC251  0_0402_5%  [R_0402]  79.41 62.82 180 bottom
RC252  51_0201_5%  [R_0201]  71.79 62.25 270 bottom
RC253  1.5K_0201_5%  [R_0201]  70.4 67.54 90 top
RC254  51_0201_5%  [R_0201]  75.6 62.25 270 bottom
RC255  100_0201_5%  [R_0201]  76.24 62.25 270 bottom
RC256  1K_0201_5%  [R_0201]  58.8 65.47 0 top
RC257  1K_0201_5%  [R_0201]  70.52 62.25 270 bottom
RC258  51_0201_5%  [R_0201]  50.53 66.08 90 top
RC366  15_0201_1%  [R_0201]  102.91 39.92 90 top
RC367  15_0201_1%  [R_0201]  102.34 39.92 90 top
RC368  15_0201_1%  [R_0201]  101.76 39.92 90 top
RC369  15_0201_1%  [R_0201]  100.56 39.92 90 top
RC370  0_0201_5%  [R_0201]  59.07 66.1 90 top
RC371  1K_0201_5%  [R_0201]  62.5 66.43 90 top
RC375  33_0201_1%  [R_0201]  108.33 58.45 90 bottom
RC376  33_0201_1%  [R_0201]  107.77 58.45 90 bottom
RC381  100K_0201_5%  [R_0201]  98.2 12.88 0 top
RC383  0_0201_5%  [R0201_0OHM]  60.62 29.72 270 bottom
RC387  0_0201_5%  [R_0201]  118.02 31.58 0 bottom
RC388  0_0201_5%  [R_0201]  120.78 33.42 0 bottom
RC394  0_0201_5%  [R_0201]  116.46 43.62 0 bottom
RC395  10K_0201_5%  [R_0201]  112.28 48.09 180 bottom
RC397  20K_0201_5%  [R_0201]  105.12 46.37 270 top
RC402  60.4_0201_1%  [R_0201]  106.59 57.45 90 bottom
RC403  33_0201_1%  [R_0201]  98.53 27.83 270 bottom
RC404  33_0201_1%  [R_0201]  97.89 27.83 270 bottom
RC405  1K_0201_1%  [R_0201]  73.06 61.04 270 bottom
RC406  1K_0201_1%  [R_0201]  74.33 62.25 270 bottom
RC407  1K_0201_1%  [R_0201]  73.06 62.25 270 bottom
RC408  1K_0201_1%  [R_0201]  67.35 62.25 270 bottom
RC409  1K_0201_1%  [R_0201]  69.25 61.04 270 bottom
RC410  1K_0201_1%  [R_0201]  67.98 62.25 270 bottom
RC411  1K_0201_1%  [R_0201]  69.25 62.25 270 bottom
RC412  1K_0201_1%  [R_0201]  73.7 61.04 270 bottom
RC413  1K_0201_1%  [R_0201]  69.89 61.04 270 bottom
RC414  1K_0201_1%  [R_0201]  73.7 62.25 270 bottom
RC415  1K_0201_1%  [R_0201]  69.89 62.25 270 bottom
RC416  1K_0201_1%  [R_0201]  67.35 61.04 270 bottom
RC417  1K_0201_1%  [R_0201]  68.62 61.04 270 bottom
RC418  1K_0201_1%  [R_0201]  67.98 61.04 270 bottom
RC419  1K_0201_1%  [R_0201]  68.62 62.25 270 bottom
RC420  0_0201_5%  [R_0201]  61.73 33.17 180 bottom
RC424  0_0201_5%  [R_0201]  115.72 43.62 180 bottom
RC425  0_0201_5%  [R0201_0OHM]  91.93 51.64 90 top
RC426  0_0201_5%  [R0201_0OHM]  93.05 51.64 90 top
RC429  0_0201_5%  [R0201_0OHM]  84.56 52.69 90 top
RC430  0_0201_5%  [R0201_0OHM]  84.64 52.03 180 top
RC431  0_0201_5%  [R0201_0OHM]  66.18 58.5 90 bottom
RC432  0_0201_5%  [R0201_0OHM]  66.75 58.5 90 bottom
RC433  100K_0201_5%  [R_0201]  95.8 12.88 0 top
RC434  0_0201_5%  [R_0201]  79.95 39.83 0 top
RC435  0_0201_5%  [R_0201]  79.95 40.42 0 top
RC436  100K_0201_5%  [R_0201]  78.68 39.83 0 top
RC439  150_0201_1%  [R_0201]  112.37 36.85 180 bottom
RC443  4.7K_0201_5%  [R_0201]  105.76 39.92 90 top
RC444  20K_0201_5%  [R_0201]  105.19 39.92 90 top
RC445  4.7K_0201_5%  [R_0201]  112.32 39.25 270 bottom
RC446  20K_0201_5%  [R_0201]  111.73 39.25 270 bottom
RC451  4.7K_0201_5%  [R_0201]  98.84 39.92 90 top
RC452  4.7K_0201_5%  [R_0201]  98.27 39.92 90 top
RC454  20K_0201_5%  [R_0201]  97.74 27.6 270 top
RC458  10K_0201_5%  [R_0201]  106.77 52.04 270 top
RC459  10K_0201_5%  [R_0201]  106.77 52.67 90 top
RC460  10K_0201_5%  [R_0201]  106.78 50.76 0 top
RC463  100K_0201_5%  [R_0201]  112.36 50.86 180 bottom
RC464  20K_0201_5%  [R_0201]  112.32 39.85 180 bottom
RC465  100K_0201_5%  [R_0201]  98.31 27.6 270 top
RC466  4.99_0201_1%  [R_0201]  107.23 28.75 90 bottom
RC467  4.99_0201_1%  [R_0201]  105.38 28.85 90 bottom
RC468  4.99_0201_1%  [R_0201]  104.75 28.85 90 bottom
RC469  4.99_0201_1%  [R_0201]  107.29 27.45 90 bottom
RC470  4.99_0201_1%  [R_0201]  106.02 28.85 90 bottom
RC471  0_0201_5%  [R0201_0OHM]  105.96 30.02 90 bottom
RC472  0_0201_5%  [R0201_0OHM]  108.5 28.34 90 top
RC473  49.9_0201_1%  [R_0201]  104.11 15.86 90 top
RC474  49.9_0201_1%  [R_0201]  104.11 14.59 90 top
RC475  49.9_0201_1%  [R_0201]  114.34 13.7 90 top
RC476  49.9_0201_1%  [R_0201]  114.34 14.97 90 top
RC477  49.9_0201_1%  [R_0201]  104.11 13.32 90 top
RC481  100K_0201_5%  [R_0201]  106.53 30.02 90 bottom
RC482  100K_0201_5%  [R_0201]  104.18 29.39 270 bottom
RC483  100K_0201_5%  [R_0201]  106.65 28.09 270 bottom
RC484  100K_0201_5%  [R_0201]  106.65 29.36 270 bottom
RC485  4.7K_0201_5%  [R_0201]  104.49 30.6 270 bottom
RC486  4.7K_0201_5%  [R_0201]  106.02 28.09 270 bottom
RC487  4.7K_0201_5%  [R_0201]  105.32 30.6 270 bottom
RC488  2.2K_0201_5%  [R_0201]  119.23 31.58 90 bottom
RC489  2.2K_0201_5%  [R_0201]  122.4 32.78 270 bottom
RC490  4.7K_0201_5%  [R_0201]  218.73 31.93 270 top
RC491  20K_0201_5%  [R_0201]  219.37 31.93 270 top
RC499  100K_0201_5%  [R_0201]  110.34 43.81 270 top
RC500  100K_0201_5%  [R_0201]  110.34 44.49 90 top
RC501  SHORT PADS  [SHORTPADS]  111.86 43.39 180 top
RC502  SHORT PADS  [SHORTPADS]  111.8 45.23 180 top
RC503  100K_0201_5%  [R_0201]  112.28 47.52 180 bottom
RC511  1K_0201_5%  [R_0201]  24.32 6.5 0 top
RC512  0_0201_5%  [R0201_0OHM]  26.17 6.5 180 top
RC516  10K_0201_5%  [R_0201]  110.9 58.96 180 bottom
RC517  0_0201_5%  [R_0201]  111.53 58.96 0 bottom
RC518  10K_0201_5%  [R_0201]  102.67 28.81 90 bottom
RC519  1K_0201_5%  [R_0201]  60.81 66.99 270 top
RC521  150_0201_1%  [R_0201]  60.24 66.4 90 top
RC522  1.5K_0201_5%  [R_0201]  59.07 67.27 180 top
RC523  1K_0201_5%  [R_0201]  53.61 66.63 270 top
RC524  33_0201_5%  [R_0201]  105.61 43.96 180 top
RC525  33_0201_5%  [R_0201]  108.85 44.21 180 top
RC526  20K_0201_5%  [R_0201]  107.07 43.92 270 top
RC527  20K_0201_5%  [R_0201]  106.46 44 270 top
RC528  75K_0201_5%  [R_0201]  108.5 29.95 90 top
RC529  71.5K_0201_1%  [R_0201]  107.48 40.51 270 top
RC530  10K_0201_5%  [R_0201]  105.45 29.86 90 top
RC531  10K_0201_5%  [R_0201]  109.22 53 180 top
RC534  0_0402_5%  [R0402_0OHM]  92.63 58.36 180 bottom
RC538  499K_0201_1%  [R_0201]  117.72 42.39 0 bottom
RC539  49.9K_0201_1%  [R_0201]  113.79 49.03 90 bottom
RC540  100K_0201_5%  [R_0201]  117.69 48.96 90 bottom
RC541  0_0402_5%  [R_0402]  99.43 44 180 top
RC542  0_0402_5%  [R0402_0OHM]  99.43 44.81 180 top
RC545  100K_0201_5%  [R_0201]  102.02 29.39 270 bottom
RC546  10K_0201_5%  [R_0201]  101.45 29.39 270 bottom
RC547  10K_0201_5%  [R_0201]  103.76 31.73 270 top
RC548  10K_0201_5%  [R_0201]  100.81 26.43 270 bottom
RC549  10K_0201_5%  [R_0201]  101.45 30.6 270 bottom
RC550  10K_0201_5%  [R_0201]  102.08 30.6 270 bottom
RC551  10K_0201_5%  [R_0201]  102.72 30.6 270 bottom
RC555  1K_0201_5%  [R_0201]  106.6 42.77 180 top
RC556  1K_0201_5%  [R_0201]  105.75 43.39 180 top
RC559  33_0201_1%  [R_0201]  94.33 29.99 90 bottom
RC560  10K_0201_5%  [R_0201]  105.79 41.23 0 top
RC564  10K_0201_5%  [R_0201]  104.32 31.15 90 top
RC565  33_0201_5%  [R_0201]  112.27 41.2 180 bottom
RC566  0_0201_5%  [R0201_0OHM]  112.27 40.65 180 bottom
RC568  10K_0201_5%  [R_0201]  99.54 30.63 270 bottom
RC569  100K_0201_5%  [R_0201]  101.07 27.2 90 bottom
RC570  100K_0201_5%  [R_0201]  99.99 40.51 270 top
RC571  100K_0201_5%  [R_0201]  100.43 27.2 90 bottom
RC572  100K_0201_5%  [R_0201]  102.77 29.32 90 top
RC573  100K_0201_5%  [R_0201]  119.01 27.07 180 bottom
RC574  0_0201_5%  [R0201_0OHM]  120.29 50.78 90 bottom
RC575  0_0201_5%  [R0201_0OHM]  116.71 27.18 270 bottom
RC576  0_0201_5%  [R0201_0OHM]  127.17 43.65 90 bottom
RC577  100K_0201_5%  [R_0201]  102.87 31.13 90 top
RC580  499_0201_1%  [R_0201]  105.79 47.53 0 top
RC581  499_0201_1%  [R_0201]  104.43 46.46 90 top
RC582  100K_0201_5%  [R_0201]  124.4 42.75 90 bottom
RC583  10K_0201_5%  [R_0201]  104.59 50.09 270 top
RC584  10K_0201_5%  [R_0201]  104.01 50.09 270 top
RC585  10K_0201_5%  [R_0201]  109.05 49.27 270 top
RC594  1K_0201_5%  [R_0201]  108.52 40.91 0 top
RC595  1K_0201_5%  [R_0201]  108.46 41.55 0 top
RC596  10K_0201_5%  [R_0201]  112.37 50.27 180 bottom
RC597  20K_0201_5%  [R_0201]  220.64 31.93 270 top
RC599  0_0201_5%  [R_0201]  117.28 26.6 90 bottom
RC604  0_0201_5%  [R_0201]  115.72 42.8 180 bottom
RC606  20K_0201_5%  [R_0201]  107.03 46.28 270 top
RC607  20K_0201_5%  [R_0201]  104.62 39.92 90 top
RC608  100K_0201_5%  [R_0201]  109.77 41.71 270 top
RC609  10K_0201_5%  [R_0201]  110.35 41.73 0 top
RC611  10K_0201_5%  [R_0201]  102.93 27.13 270 top
RC612  0_0201_5%  [R0201_0OHM]  122.66 34 180 bottom
RC613  100K_0201_5%  [R_0201]  96.87 28.72 90 bottom
RC614  75K_0201_5%  [R_0201]  111.54 40.02 90 top
RC615  100K_0201_5%  [R_0201]  94.96 30.04 90 bottom
RC616  100K_0201_5%  [R_0201]  102.28 27.63 270 top
RC617  10K_0201_5%  [R_0201]  107.48 26.88 180 bottom
RC618  10K_0201_5%  [R_0201]  116.38 27.92 0 bottom
RC619  10K_0201_5%  [R_0201]  112.37 49.64 180 bottom
RC620  10K_0201_5%  [R_0201]  106.65 31.17 270 top
RC621  0_0201_5%  [R_0201]  124.73 33.6 270 bottom
RC622  100K_0201_5%  [R_0201]  122.66 33.42 180 bottom
RC623  10K_0201_5%  [R_0201]  113.07 51.72 0 bottom
RC624  10K_0201_5%  [R_0201]  113.07 52.29 0 bottom
RC625  0_0201_5%  [R_0201]  124.73 31.77 90 bottom
RC626  0_0201_5%  [R0201_0OHM]  111.87 30.33 180 top
RC627  0_0402_5%  [R0402_0OHM]  97.33 50.78 270 top
RC628  0_0402_5%  [R0402_0OHM]  102.16 12.79 90 top
RC630  0_0201_5%  [R_0201]  117.56 29.27 270 bottom
RC631  0_0201_5%  [R0201_0OHM]  129.11 31.04 0 bottom
RC632  0_0201_5%  [R_0201]  107.8 28.75 90 bottom
RC633  10K_0201_5%  [R_0201]  105.17 53.25 270 top
RC634  10K_0201_5%  [R_0201]  103.34 29.37 0 top
RD1  240_0201_1%  [R_0201]  60.04 15.43 270 top
RD2  240_0201_1%  [R_0201]  59.48 15.43 270 top
RD3  24.9_0201_1%  [R_0201]  70.57 29 90 bottom
RD4  8.2K_0201_1%  [R_0201]  58.18 18.94 180 top
RD5  10_0201_1%  [R_0201]  69.35 30.75 270 bottom
RD6  8.2K_0201_1%  [R_0201]  58.19 17.77 90 top
RD7  240_0201_1%  [R_0201]  95.14 15.43 270 bottom
RD8  240_0201_1%  [R_0201]  94.59 15.43 270 bottom
RD9  24.9_0201_1%  [R_0201]  57 28.47 270 top
RD10  4.99_0201_1%  [R_0201]  57.63 28.47 270 top
RD11  8.2K_0201_1%  [R_0201]  57.63 27.2 0 top
RD12  8.2K_0201_1%  [R_0201]  58.14 26.56 180 top
RD13  240_0201_1%  [R_0201]  84.24 15.43 270 top
RD14  240_0201_1%  [R_0201]  83.68 15.43 270 top
RD15  10_0201_1%  [R_0201]  68.24 30.75 270 bottom
RD16  8.2K_0201_1%  [R_0201]  68.49 29.59 270 bottom
RD17  24.9_0201_1%  [R_0201]  69.07 29.59 270 bottom
RD18  8.2K_0201_1%  [R_0201]  67.42 29.59 270 bottom
RD19  240_0201_1%  [R_0201]  70.72 15.43 270 bottom
RD20  240_0201_1%  [R_0201]  70.16 15.43 270 bottom
RD21  68_0201_1%  [R_0201]  60.95 15.43 270 bottom
RD22  68_0201_1%  [R_0201]  93.18 15.43 270 top
RD23  68_0201_1%  [R_0201]  61.51 15.43 270 bottom
RD24  68_0201_1%  [R_0201]  92.62 15.43 270 top
RD25  68_0201_1%  [R_0201]  62.63 15.43 270 bottom
RD26  68_0201_1%  [R_0201]  91.51 15.43 270 top
RD27  68_0201_1%  [R_0201]  62.07 15.43 270 bottom
RD28  68_0201_1%  [R_0201]  92.06 15.43 270 top
RD29  68_0201_1%  [R_0201]  63.18 15.43 270 bottom
RD30  68_0201_1%  [R_0201]  90.95 15.43 270 top
RD31  68_0201_1%  [R_0201]  67.37 15.43 270 bottom
RD32  68_0201_1%  [R_0201]  87.04 15.43 270 top
RD33  68_0201_1%  [R_0201]  68.49 15.43 270 bottom
RD34  68_0201_1%  [R_0201]  85.92 15.43 270 top
RD35  68_0201_1%  [R_0201]  67.93 15.43 270 bottom
RD36  68_0201_1%  [R_0201]  86.48 15.43 270 top
RD37  68_0201_1%  [R_0201]  69.05 15.43 270 bottom
RD38  68_0201_1%  [R_0201]  85.36 15.43 270 top
RD39  68_0201_1%  [R_0201]  69.6 15.43 270 bottom
RD40  68_0201_1%  [R_0201]  84.8 15.43 270 top
RD41  68_0201_1%  [R_0201]  69.54 15.43 270 top
RD42  68_0201_1%  [R_0201]  84.45 15.43 270 bottom
RD43  68_0201_1%  [R_0201]  68.98 15.43 270 top
RD44  68_0201_1%  [R_0201]  85.57 15.43 270 bottom
RD45  68_0201_1%  [R_0201]  67.86 15.43 270 top
RD46  68_0201_1%  [R_0201]  86.69 15.43 270 bottom
RD47  68_0201_1%  [R_0201]  68.42 15.43 270 top
RD48  68_0201_1%  [R_0201]  85.01 15.43 270 bottom
RD49  68_0201_1%  [R_0201]  67.31 15.43 270 top
RD50  68_0201_1%  [R_0201]  86.13 15.43 270 bottom
RD51  68_0201_1%  [R_0201]  62.84 15.43 270 top
RD52  68_0201_1%  [R_0201]  91.23 15.43 270 bottom
RD53  68_0201_1%  [R_0201]  61.72 15.43 270 top
RD54  68_0201_1%  [R_0201]  92.35 15.43 270 bottom
RD55  68_0201_1%  [R_0201]  62.28 15.43 270 top
RD56  68_0201_1%  [R_0201]  91.79 15.43 270 bottom
RD57  68_0201_1%  [R_0201]  61.16 15.43 270 top
RD58  68_0201_1%  [R_0201]  92.91 15.43 270 bottom
RD59  68_0201_1%  [R_0201]  60.6 15.43 270 top
RD60  68_0201_1%  [R_0201]  93.47 15.43 270 bottom
RD61  80.6_0201_1%~D  [R_0201]  64.51 15.43 270 top
RD62  80.6_0201_1%~D  [R_0201]  87.24 15.43 270 bottom
RD63  80.6_0201_1%~D  [R_0201]  63.39 15.43 270 top
RD64  80.6_0201_1%~D  [R_0201]  90.67 15.43 270 bottom
RD65  80.6_0201_1%~D  [R_0201]  64.3 15.43 270 bottom
RD66  80.6_0201_1%~D  [R_0201]  90.39 15.43 270 top
RD67  80.6_0201_1%~D  [R_0201]  63.74 15.43 270 bottom
RD68  80.6_0201_1%~D  [R_0201]  89.83 15.43 270 top
RD69  80.6_0201_1%~D  [R_0201]  66.19 15.43 270 top
RD70  80.6_0201_1%~D  [R_0201]  87.8 15.43 270 bottom
RD71  80.6_0201_1%~D  [R_0201]  66.75 15.43 270 top
RD72  80.6_0201_1%~D  [R_0201]  88.36 15.43 270 bottom
RD73  80.6_0201_1%~D  [R_0201]  65.72 29.1 0 top
RD74  80.6_0201_1%~D  [R_0201]  93.88 15.36 0 top
RD75  37.4_0201_1%~D  [R_0201]  64.86 15.43 270 bottom
RD76  37.4_0201_1%~D  [R_0201]  88.71 15.43 270 top
RD77  37.4_0201_1%~D  [R_0201]  65.42 15.43 270 bottom
RD78  37.4_0201_1%~D  [R_0201]  89.27 15.43 270 top
RD79  37.4_0201_1%~D  [R_0201]  65.07 15.43 270 top
RD80  37.4_0201_1%~D  [R_0201]  89.48 15.43 270 bottom
RD81  37.4_0201_1%~D  [R_0201]  65.63 15.43 270 top
RD82  37.4_0201_1%~D  [R_0201]  88.92 15.43 270 bottom
RE1  10K_0201_5%  [R_0201]  256.26 56.79 180 top
RE90  0_0201_5%  [R0201_0OHM]  239.66 69.37 270 top
RE91  10K_0201_5%  [R_0201]  236.08 72.62 270 top
RE92  10K_0201_5%  [R_0201]  232.57 72.62 270 top
RE93  10K_0201_5%  [R_0201]  234.3 72.62 270 top
RE94  10K_0201_5%  [R_0201]  233.16 72.62 270 top
RE95  10K_0201_5%  [R_0201]  233.73 72.04 90 top
RE96  0_0201_5%  [R_0201]  232 72.62 270 top
RE97  0_0201_5%  [R0201_0OHM]  235.48 72.04 180 top
RE98  0_0201_5%  [R_0201]  224.5 69.45 270 top
RE99  0_0201_5%  [R0201_0OHM]  225.13 69.45 270 top
RE103  0_0402_5%  [R0402_0OHM]  260.13 64.99 270 top
RE104  2.2K_0201_5%  [R_0201]  264.9 63.48 90 top
RE105  2.2K_0201_5%  [R_0201]  260.43 60.53 180 top
RE106  100K_0201_5%  [R_0201]  275.59 59.01 0 top
RE108  2.2K_0201_5%  [R_0201]  261.47 49.33 270 top
RE109  2.2K_0201_5%  [R_0201]  260.9 49.33 270 top
RE110  2.2K_0201_5%  [R_0201]  269.59 65.64 90 top
RE111  2.2K_0201_5%  [R_0201]  270.17 65.64 90 top
RE112  0_0201_5%  [R_0201]  276.17 60.79 180 top
RE113  100K_0201_5%  [R_0201]  262.61 47.9 270 top
RE114  100_0402_1%  [R_0402]  258.8 55.9 180 top
RE115  43K_0201_1%  [R_0201]  262.61 48.75 90 top
RE116  100K_0201_5%  [R_0201]  274.36 54.63 0 top
RE118  100K_0201_5%  [R_0201]  259.22 54.63 180 top
RE119  100K_0201_5%  [R_0201]  274.38 51.52 0 top
RE120  10K_0201_5%  [R_0201]  274.38 50.95 0 top
RE121  100K_0201_5%  [R_0201]  271.88 65.64 90 top
RE122  10K_0201_5%  [R_0201]  271.75 63.35 90 top
RE123  300_0402_5%  [R_0402]  259.88 49.32 270 top
RE124  10K_0201_5%  [R_0201]  274.38 49.8 0 top
RE125  300_0402_5%  [R_0402]  257.82 49.66 90 top
RE126  100K_0201_5%  [R_0201]  274.38 60.79 0 top
RE129  100K_0201_5%  [R_0201]  274.38 59.01 0 top
RE131  100K_0201_5%  [R_0201]  260.43 59.39 180 top
RE135  100K_0201_5%  [R_0201]  265.47 63.48 90 top
RE136  100K_0201_5%  [R_0201]  259.22 59.39 180 top
RE138  100K_0201_5%  [R_0201]  259.84 59.96 0 top
RE141  10K_0201_5%  [R_0201]  265.91 49.46 270 top
RE142  4.7K_0201_5%  [R_0201]  278.74 56.15 180 top
RE144  0_0201_5%  [R0201_0OHM]  275.59 55.01 0 top
RE147  10K_0201_5%  [R_0201]  257.43 54.06 0 top
RE148  10K_0201_5%  [R_0201]  258.52 50.06 90 top
RE149  1K_0201_5%  [R_0201]  259.84 61.68 0 top
RE151  43_0201_5%  [R_0201]  87.32 57.8 180 bottom
RE153  100K_0201_5%  [R_0201]  260.43 62.25 180 top
RE154  100K_0201_5%  [R_0201]  260.41 58.82 180 top
RE155  100K_0201_5%  [R_0201]  260.43 61.11 180 top
RE158  0_0201_5%  [R0201_0OHM]  257.43 54.63 0 top
RE161  100_0201_5%  [R_0201]  274.36 55.77 0 top
RE162  100K_0201_5%  [R_0201]  277.47 56.7 270 top
RE163  100K_0201_5%  [R_0201]  259.89 51.52 0 top
RE164  100_0201_1%  [R_0201]  276.9 56.11 90 top
RE165  0_0201_5%  [R0201_0OHM]  113.05 20.44 0 bottom
RE166  100K_0201_5%  [R_0201]  260.48 52.09 180 top
RE167  0_0201_5%  [R0201_0OHM]  130.01 51.72 270 bottom
RE172  10K_0201_5%  [R_0201]  256.27 54.31 180 top
RE177  100K_0201_5%  [R_0201]  250.48 51.96 270 top
RE179  0_0201_5%  [R0201_0OHM]  264.17 63.39 180 top
RE180  33_0201_5%  [R_0201]  257.4 58.69 180 top
RE182  0_0201_5%  [R0201_0OHM]  115.02 53.37 180 bottom
RE183  0_0603_5%  [R0603_0OHM]  275.94 58.12 180 top
RE184  0_0603_5%  [R0603_0OHM]  264.45 47.9 90 top
RE186  10K_0201_5%  [R_0201]  259.29 51.52 180 top
RE187  100K_0201_5%  [R_0201]  265.47 65.27 270 top
RE188  0_0402_5%  [R0402_0OHM]  257.83 52.79 0 top
RE189  0_0402_5%  [R_0402]  259.49 52.79 0 top
RE190  1K_0201_5%  [R_0201]  267.22 65.11 180 top
RE192  100K_0201_5%  [R_0201]  271.82 47.61 90 top
RE193  0_0201_5%  [R0201_0OHM]  271.12 47.61 90 top
RE197  8.2K_0201_5%  [R_0201]  250.48 53.66 90 top
RE198  2.2K_0201_5%  [R_0201]  105.82 65.75 90 top
RE199  0_0201_5%  [R0201_0OHM]  105.82 64.54 90 top
RE200  240K_0402_5%  [R_0402]  277.09 53.61 180 top
RE209  10K_0201_5%  [R_0201]  236.7 72.62 270 top
RE210  10K_0201_5%  [R_0201]  237.27 72.62 270 top
RE211  10K_0201_5%  [R_0201]  237.91 72.62 270 top
RE212  10K_0201_5%  [R_0201]  238.48 72.62 270 top
RE213  100_0201_5%  [R_0201]  254.45 51.9 270 top
RE241  100K_0201_5%  [R_0201]  56.32 29.64 270 bottom
RE457  0_0201_5%  [R0201_0OHM]  255.7 55.56 270 top
RE467  0_0201_5%  [R0201_0OHM]  276.17 59.58 180 top
RE468  0_0201_5%  [R0201_0OHM]  274.97 61.99 180 top
RE469  0_0201_5%  [R0201_0OHM]  266.64 63.96 0 top
RE472  1M_0201_5%  [R_0201]  266.04 63.48 90 top
RE473  100K_0201_5%  [R_0201]  115.01 52.79 180 bottom
RE474  1.58K_0402_1%  [R_0402]  273.01 63.52 0 top
RE477  0_0201_5%  [R0201_0OHM]  256.31 55.56 270 top
RE478  0_0201_5%  [R0201_0OHM]  255.71 56.15 0 top
RE480  0_0201_5%  [R0201_0OHM]  267.38 48.19 270 top
RE482  0_0201_5%  [R0201_0OHM]  274.97 50.37 180 top
RE484  0_0201_5%  [R0201_0OHM]  276.17 60.15 180 top
RE485  0_0201_5%  [R0201_0OHM]  272.39 48.88 90 top
RE486  2.2K_0201_5%  [R_0201]  259.22 58.82 180 top
RE487  2.2K_0201_5%  [R_0201]  254.67 59.45 90 top
RE488  100K_0201_5%  [R_0201]  278.74 56.79 180 top
RE489  10K_0201_5%  [R_0201]  274.38 52.09 0 top
RE490  100K_0201_5%  [R_0201]  278.74 57.37 180 top
RE495  2.2K_0201_5%  [R_0201]  271.31 65.64 90 top
RE496  2.2K_0201_5%  [R_0201]  270.74 65.64 90 top
RE497  100K_0201_5%  [R_0201]  272.96 48.19 270 top
RE499  100K_0201_5%  [R_0201]  267.37 49.46 270 top
RE500  100K_0201_5%  [R_0201]  275.59 61.36 0 top
RE501  100K_0201_5%  [R_0201]  270.48 48.15 270 top
RE502  100K_0201_5%  [R_0201]  268.58 49.46 270 top
RE503  100K_0201_5%  [R_0201]  259.18 58.18 180 top
RE504  100K_0201_5%  [R_0201]  270.55 49.45 270 top
RE505  100K_0201_5%  [R_0201]  259.22 53.49 180 top
RE506  100K_0201_5%  [R_0201]  269.98 46.88 0 top
RE507  0_0201_5%  [R0201_0OHM]  120.94 50.82 0 bottom
RE508  0_0201_5%  [R0201_0OHM]  256.26 57.42 180 top
RE509  100K_0201_5%  [R_0201]  292.45 58.73 270 bottom
RE511  0_0201_5%  [R0201_0OHM]  41.78 38.75 0 top
RE512  0_0201_5%  [R0201_0OHM]  293.64 58.12 180 bottom
RE513  0_0201_5%  [R0201_0OHM]  263.5 48.79 90 top
RE515  100K_0201_5%  [R_0201]  259.22 59.96 180 top
RE516  100K_0201_5%  [R_0201]  268.58 48.19 270 top
RE518  100K_0201_5%  [R_0201]  276.58 52.85 0 top
RE519  100K_0201_5%  [R_0201]  276.33 48.98 0 top
RE521  10K_0201_5%  [R_0201]  262.04 49.33 270 top
RE522  100K_0201_5%  [R_0201]  269.21 48.15 270 top
RE524  100K_0201_5%  [R_0201]  259.22 60.53 180 top
RE525  100K_0201_5%  [R_0201]  274.97 60.15 180 top
RE526  100K_0201_5%  [R_0201]  271.82 49.46 270 top
RE527  100K_0201_5%  [R_0201]  260.49 54.63 180 top
RE529  100K_0201_5%  [R_0201]  274.38 61.36 0 top
RE530  100K_0201_5%  [R_0201]  277.47 57.3 180 top
RE531  0_0201_5%  [R_0201]  259.12 62.12 180 top
RE532  0_0201_5%  [R0201_0OHM]  272.96 49.46 270 top
RE533  240K_0402_5%  [R_0402]  256.61 60.9 270 top
RE534  0_0201_5%  [R0201_0OHM]  256.3 58.06 180 top
RE535  100K_0201_5%  [R_0201]  274.38 49.15 0 top
RE536  0_0402_5%  [R0402_0OHM]  274.43 52.95 0 top
RH51  10K_0201_5%  [R_0201]  113.44 42.53 180 bottom
RH52  10K_0201_5%  [R_0201]  111.68 42.53 0 bottom
RH53  10K_0201_5%  [R_0201]  113.44 41.84 180 bottom
RH54  10K_0201_5%  [R_0201]  111.68 41.84 0 bottom
RH55  10K_0201_5%  [R_0201]  113.44 43.21 180 bottom
RH56  10K_0201_5%  [R_0201]  111.68 43.21 0 bottom
RH57  10K_0201_5%  [R_0201]  113.44 43.9 180 bottom
RH58  10K_0201_5%  [R_0201]  111.68 43.9 0 bottom
RH59  10K_0201_5%  [R_0201]  113.44 44.59 180 bottom
RH60  10K_0201_5%  [R_0201]  111.68 44.59 0 bottom
RI29  4.99K_0201_1%  [R_0201]  289.53 42.14 90 top
RI30  0_0201_5%  [R_0201]  283.15 44.98 0 top
RI38  4.7K_0201_5%  [R_0201]  287.63 49.89 90 top
RI40  4.7K_0201_5%  [R_0201]  286.99 49.89 90 top
RI42  4.7K_0201_5%  [R_0201]  286.36 49.89 90 top
RI44  4.7K_0201_5%  [R_0201]  285.72 49.89 90 top
RI48  0_0201_5%  [R0201_0OHM]  296.54 53.42 0 top
RI49  0_0201_5%  [R0201_0OHM]  296.54 54.06 0 top
RI50  0_0201_5%  [R0201_0OHM]  296.54 55.64 0 top
RI51  0_0201_5%  [R0201_0OHM]  296.54 55.01 0 top
RI53  10K_0201_5%  [R_0201]  284.03 61.04 0 top
RI55  22.1K_0201_1%  [R_0201]  287.03 64.73 180 top
